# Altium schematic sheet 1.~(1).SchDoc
size 246 x 182 mm; Organization: Altium Limited; Address1: L3, 12a Rodborough Rd; Address2: Frenchs Forest; Address3: NSW; Address4: Australia 2086
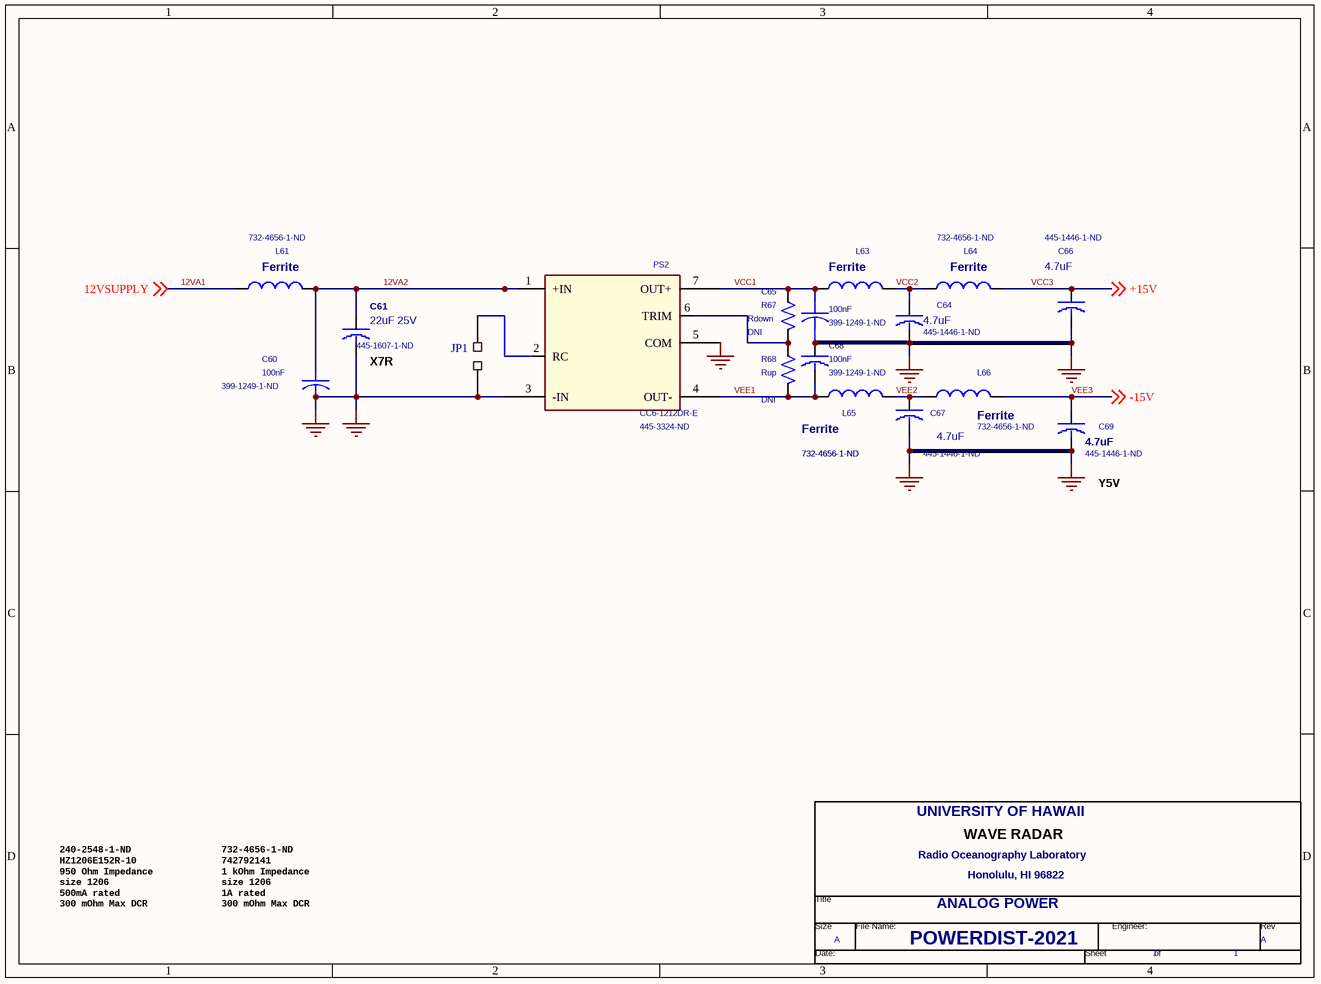
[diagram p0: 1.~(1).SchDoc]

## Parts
*  Doc: POWERDIST-2021  RevCode: A  Title: ANALOG POWER  OrgName: UNIVERSITY OF HAWAII  OrgAddr1: Radio Oceanography Laboratory  OrgAddr3: Honolulu, HI 96822  Page Number: 1  (hidden comment: HWRadar)  (graphical)
C60  100nF  DK Stock: 399-1249-1-ND  [1206]
C61  22uF 25V  DK Stock: 445-1607-1-ND  [1812]
C64  4.7uF  DK Stock: 445-1446-1-ND  [1812]
C65  100nF  DK Stock: 399-1249-1-ND  [1206]
C66  4.7uF  DK Stock: 445-1446-1-ND  [1812]
C67  4.7uF  DK Stock: 445-1446-1-ND  [1812]
C68  100nF  DK Stock: 399-1249-1-ND  [1206]
C69  4.7uF  DK Stock: 445-1446-1-ND  [1812]
JP1  (no value)  [2X2.54]
L61  Ferrite  DK Stock: 732-4656-1-ND  [1206]
L63  Ferrite  DK Stock: 732-4656-1-ND  [1206]
L64  Ferrite  DK Stock: 732-4656-1-ND  [1206]
L65  Ferrite  DK Stock: 732-4656-1-ND  [1206]
L66  Ferrite  DK Stock: 732-4656-1-ND  [1206]
PS2  CC6-1212DR-E  DK Stock: 445-3324-ND  [DCDC-CC6/B]
R67  Rdown  DK Stock: DNI  [1206]
R68  Rup  DK Stock: DNI  [1206]

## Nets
GND: C60.2 C61.2 C64.2 C65.2 C66.2 C67.2 C68.1 C69.2 JP1.1 PS2.3(-IN) PS2.5(COM)
12VA1: L61.1 ; off-sheet 12VSUPPLY  [also labelled 12VSUPPLY]
12VA2: C60.1 C61.1 L61.2 PS2.1(+IN)
VCC1: C65.1 L63.1 PS2.7(OUT+) R67.1
VCC2: C64.1 L63.2 L64.1
VCC3: C66.1 L64.2 ; off-sheet +15V  [also labelled +15V]
VEE1: C68.2 L65.1 PS2.4(OUT-) R68.2
VEE2: C67.1 L65.2 L66.1
VEE3: C69.1 L66.2 ; off-sheet -15V  [also labelled -15V]
NetJP1_2: JP1.2 PS2.2(RC)
NetPS2_6: PS2.6(TRIM) R67.2 R68.1

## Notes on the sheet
- (near C61) X7R
- (near C69) Y5V
- 240-2548-1-ND
  HZ1206E152R-10
  950 Ohm Impedance
  size 1206
  500mA rated
  300 mOhm Max DCR
- 732-4656-1-ND
  742792141
  1 kOhm Impedance
  size 1206
  1A rated
  300 mOhm Max DCR

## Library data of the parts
* = HWRadar: Engineer:: <ENG>; OrgAddr2: 2525 Correa Road
C60 C65 = CAP_SHORT
C61 C64 C66-C69 = C1206
JP1 = STRAP
L61 L63-L66 = INDUCTOR
PS2 = CONV +-15V_1
R67 R68 = R1206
